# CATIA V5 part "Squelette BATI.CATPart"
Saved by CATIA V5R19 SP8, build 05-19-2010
Part number: Squelette BATI
Publications: "Droite.4", "Droite.3", "Plan.9", "Plan.7", "Plan.5", "Plan.3", "Plan.11", "Droite.5"
Bounding box of the stored display mesh (mm): x -18 to -2, y 0 to 15.5, z -30 to 22
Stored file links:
  C:\Users\ThinkMotion\Desktop\EU_thinkMotion\iao\IAO_MMS_Groupe3\jbuffard\jbuffard\Squelette BATI.CATPart
  C:\Users\ThinkMotion\Desktop\EU_thinkMotion\iao\IAO_MMS_Groupe3\jbuffard\jbuffard\Mecanisme a coulisse a quatre elements de la griffe d'une camera.CATProduct
  C:\Users\ThinkMotion\Desktop\EU_thinkMotion\iao\IAO_MMS_Groupe3\jbuffard\jbuffard\Squelette de base.CATPart
  C:\Users\ThinkMotion\Desktop\EU_thinkMotion\iao\IAO_MMS_Groupe3\jbuffard\jbuffard\Squelette PIECE 1.CATPart
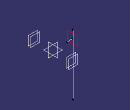
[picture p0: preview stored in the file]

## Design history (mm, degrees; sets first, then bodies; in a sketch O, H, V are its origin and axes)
Set1
  Point1: linked copy from another document
  Plane1: linked copy from another document
  Point2: linked copy from another document
  Plane2: linked copy from another document
  Point3 to Point5: linked copy from another document
  Plane3 to Plane8: linked copy from another document
  Point6: linked copy from another document
  Plane9: linked copy from another document
Set2 "Set géométrique.2"
  Line1: type PtPt, FirstPoint Point3, SecondPoint Point4
  Line2: type PtPt, FirstPoint Point5, SecondPoint Point3
  Plane10: type Offset, RefPlane Plane3, Offset 0
  Plane11: type Offset, RefPlane Plane4, Offset 0
  Plane12: type Offset, RefPlane Plane5, Offset 0
  Plane13: type Offset, RefPlane Plane6, Offset 0
  Plane14: type Offset, RefPlane Plane7, Offset 0
  Line3: type Normal, LineFirstUpto Plane9, RefPoint Point6, RefSkin Plane8, Start 0, End 0
Body1 (main body)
